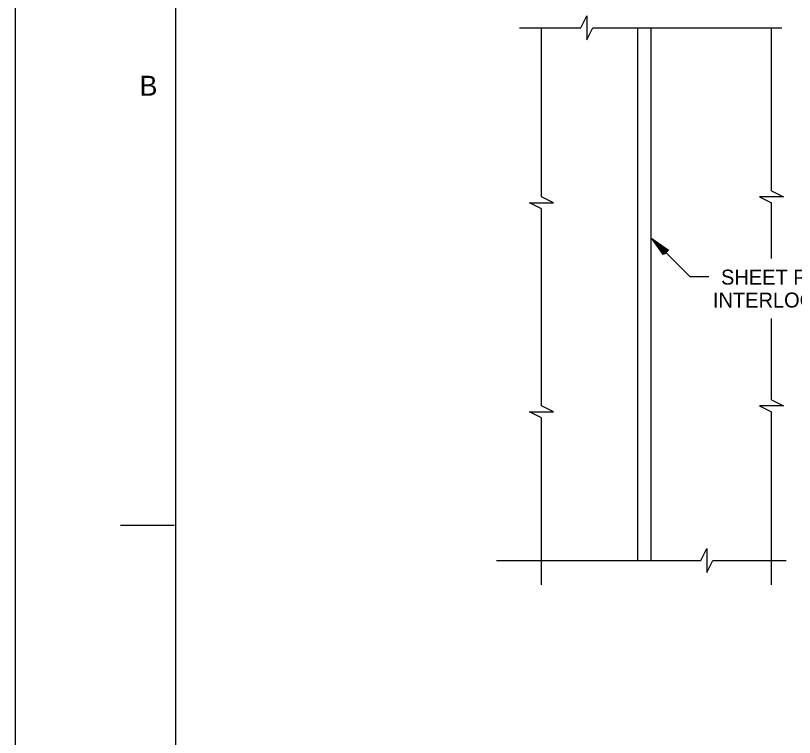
# Model space of a CAD drawing. Extents: x 22369.6 to 22428.3, y 22369.6 to 22415.
# Drawn here: x 22369.62 to 22379.34, y 22378.63 to 22387.64 of the extents above; entities that cross this region are included whole.
import ezdxf

# ---------------------------------------------------------------- set-up
doc = ezdxf.new("R2010")
doc.units = 0
for name, color, linetype in [('Level 1', 7, 'Continuous'), ('Level 10', 7, 'Continuous'), ('Level 2', 7, 'Continuous'), ('Level 4', 7, 'Continuous'), ('Level 9', 7, 'Continuous')]:
    doc.layers.add(name, color=color, linetype=linetype)

msp = doc.modelspace()

# ---------------------------------------------------------------- linework, layer by layer
at = {"layer": 'Level 1'}
for p, q in [((22375.9091, 22387.4886), (22376.6754, 22387.4886)), ((22376.1825, 22385.3773), (22376.1825, 22387.4886)), ((22376.8249, 22387.4886), (22379.1848, 22387.4886)), ((22379.0538, 22385.452), (22379.0538, 22387.4886)), ((22379.0538, 22384.6093), (22379.0538, 22385.3025)), ((22376.1825, 22382.7706), (22376.1825, 22385.2278)), ((22379.0538, 22382.8454), (22379.0538, 22383.86)), ((22379.0538, 22380.5372), (22379.0538, 22382.6959)), ((22376.1825, 22380.5372), (22376.1825, 22382.6211)), ((22375.6242, 22380.8406), (22378.1726, 22380.8406)), ((22378.3221, 22380.8406), (22379.2384, 22380.8406))]:
    msp.add_line(p, q, dxfattribs=at)
msp.add_lwpolyline([(22369.6213, 22414.9546), (22428.2885, 22414.9546), (22428.2885, 22369.6213), (22369.6213, 22369.6213)], close=True, dxfattribs=at)
for points in [[(22376.6754, 22387.4886), (22376.7499, 22387.6386), (22376.7499, 22387.339), (22376.8249, 22387.4886)], [(22376.1825, 22385.2278), (22376.0325, 22385.3023), (22376.3322, 22385.3023), (22376.1825, 22385.3773)], [(22379.0538, 22385.452), (22379.2038, 22385.3775), (22378.9042, 22385.3775), (22379.0538, 22385.3025)], [(22378.2728, 22384.3797), (22378.0402, 22384.3797), (22377.5612, 22384.8594)], [(22379.0538, 22382.8454), (22379.2038, 22382.7709), (22378.9042, 22382.7709), (22379.0538, 22382.6959)], [(22376.1825, 22382.6211), (22376.0325, 22382.6956), (22376.3322, 22382.6956), (22376.1825, 22382.7706)], [(22378.1726, 22380.8406), (22378.2471, 22380.9906), (22378.2471, 22380.6909), (22378.3221, 22380.8406)]]:
    msp.add_lwpolyline(points, dxfattribs=at)
at = {"layer": 'Level 10'}
msp.add_line((22370.9285, 22381.28), (22371.6005, 22381.28), dxfattribs=at)
at = {"layer": 'Level 2'}
for p, q in [((22377.3813, 22387.4886), (22377.3813, 22380.8406)), ((22377.5479, 22387.4886), (22377.5479, 22380.8406)), ((22377.5612, 22384.8594), (22377.5612, 22384.8594)), ((22377.6102, 22384.8103), (22377.6102, 22384.8103))]:
    msp.add_line(p, q, dxfattribs=at)
msp.add_lwpolyline([(22377.7082, 22384.6537), (22377.5612, 22384.8594), (22377.7667, 22384.7121), (22377.7167, 22384.6622), (22377.6102, 22384.8103), (22377.7497, 22384.7103), (22377.7176, 22384.6782), (22377.6573, 22384.7631), (22377.7327, 22384.7084), (22377.7195, 22384.6952), (22377.7063, 22384.7141)], dxfattribs=at)
at = {"layer": 'Level 9'}
msp.add_line((22371.6213, 22370.288), (22371.6213, 22414.288), dxfattribs=at)

# ---------------------------------------------------------------- texts
at = {"layer": 'Level 1'}
msp.add_text('B', height=0.2497, dxfattribs=at).set_placement((22371.1685, 22386.64))
at = {"layer": 'Level 4'}
for s, height, p in [('SHEET PILE', 0.18667, (22378.4242, 22384.2822)), (' INTERLOCKS', 0.186667, (22378.2541, 22383.9966))]:
    msp.add_text(s, height=height, dxfattribs=at).set_placement(p)

doc.saveas('drawing.dxf')
